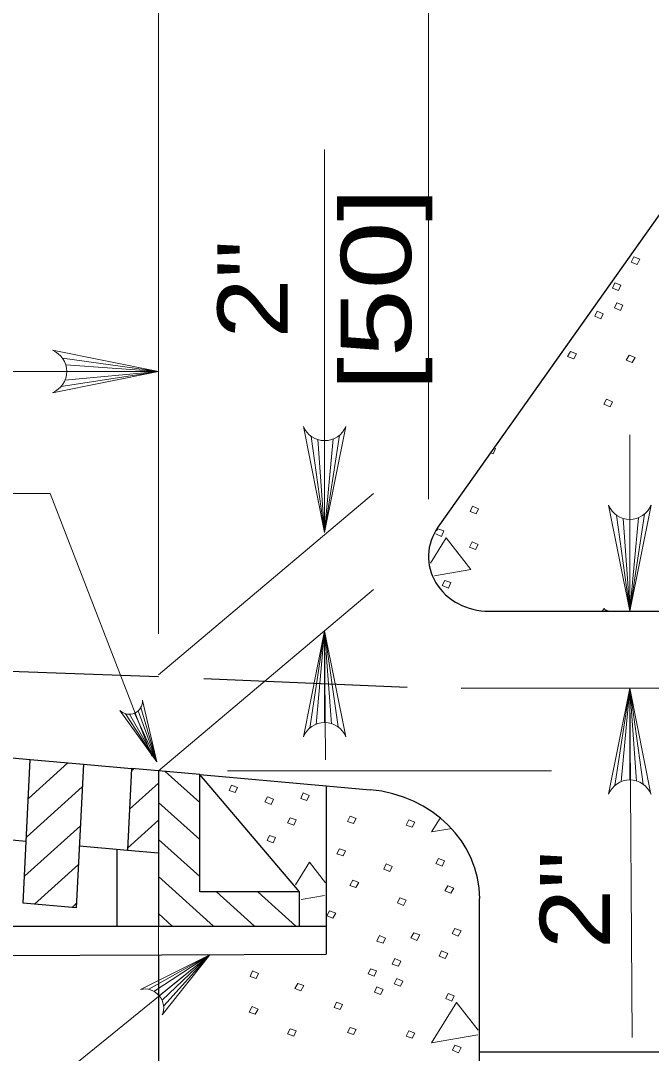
# Model space of a CAD drawing. Extents: x 1083.1 to 1123, y 697.4 to 741.4.
# Drawn here: x 1091.119 to 1092.52, y 703.761 to 706.055 of the extents above; entities that cross this region are included whole.
import ezdxf
from ezdxf.enums import TextEntityAlignment as Align

# ---------------------------------------------------------------- set-up
doc = ezdxf.new("R2010")
doc.units = 0
doc.header["$LTSCALE"] = 0.062
doc.layers.add('1', color=7, linetype='Continuous', lineweight=13)

msp = doc.modelspace()

# ---------------------------------------------------------------- linework, layer by layer
at = {"layer": '1'}
for p, q in [((1091.42492, 704.693), (1091.42492, 706.78342)), ((1092.02483, 704.99242), (1092.02483, 706.78958)), ((1091.79425, 705.769), (1091.79425, 704.91825)), ((1091.21167, 705.3055), (1091.42492, 705.27567)), ((1091.21892, 705.29067), (1091.42492, 705.27567)), ((1091.42492, 705.27567), (1088.74, 705.27567)), ((1091.20917, 705.24267), (1091.42492, 705.27567)), ((1091.21733, 705.2565), (1091.42492, 705.27567)), ((1091.22108, 705.27567), (1091.42492, 705.27567)), ((1091.76442, 705.1315), (1091.79425, 704.91825)), ((1091.77917, 705.12433), (1091.79425, 704.91825)), ((1091.82725, 705.13408), (1091.79425, 704.91825)), ((1091.81342, 705.12592), (1091.79425, 704.91825)), ((1091.79425, 705.12208), (1091.79425, 704.91825)), ((1092.47208, 705.13492), (1092.47208, 704.74317)), ((1091.053, 705.00442), (1091.18417, 705.00442)), ((1091.41017, 704.4215), (1091.18417, 705.00442)), ((1091.42492, 704.60175), (1091.90275, 705.005)), ((1092.44225, 704.95642), (1092.47208, 704.74317)), ((1092.457, 704.94925), (1092.47208, 704.74317)), ((1092.50508, 704.959), (1092.47208, 704.74317)), ((1092.49125, 704.95083), (1092.47208, 704.74317)), ((1092.47208, 704.947), (1092.47208, 704.74317)), ((1092.04342, 704.92175), (1092.04567, 704.92642)), ((1092.0645, 704.90625), (1092.02967, 704.85008)), ((1091.42492, 704.3885), (1091.90275, 704.79175)), ((1092.41492, 704.7495), (1092.41092, 704.74317)), ((1092.41983, 704.74317), (1092.41492, 704.7495)), ((1092.419, 704.74317), (1092.42008, 704.74542)), ((1092.42008, 704.74542), (1092.4255, 704.74317)), ((1091.76125, 704.48367), (1091.79425, 704.6995)), ((1091.77508, 704.49183), (1091.79425, 704.6995)), ((1091.79425, 704.6995), (1091.79617, 704.41275)), ((1091.79425, 704.49567), (1091.79425, 704.6995)), ((1091.80933, 704.49342), (1091.79425, 704.6995)), ((1091.82408, 704.48625), (1091.79425, 704.6995)), ((1092.43908, 704.35633), (1092.47208, 704.57217)), ((1092.45292, 704.3645), (1092.47208, 704.57217)), ((1092.47208, 704.57217), (1092.47733, 703.79633)), ((1092.47208, 704.36833), (1092.47208, 704.57217)), ((1092.48717, 704.36608), (1092.47208, 704.57217)), ((1092.50192, 704.35892), (1092.47208, 704.57217)), ((1091.38575, 704.52933), (1091.42117, 704.40875)), ((1091.35175, 704.5155), (1091.42117, 704.40875)), ((1091.36108, 704.51458), (1091.42117, 704.40875)), ((1091.37217, 704.51708), (1091.42117, 704.40875)), ((1091.37967, 704.52192), (1091.42117, 704.40875)), ((1091.136, 704.32733), (1091.22392, 704.40642)), ((1091.42492, 704.38842), (1091.42492, 704.3885)), ((1091.57858, 704.3885), (1092.29825, 704.3885)), ((1091.51675, 704.31825), (1091.44025, 704.38708)), ((1091.51675, 704.38025), (1091.51675, 704.38033)), ((1091.13167, 704.24117), (1091.25583, 704.35292)), ((1091.36075, 704.30333), (1091.42492, 704.36108)), ((1091.51675, 704.236), (1091.42492, 704.31858)), ((1091.35642, 704.21717), (1091.42492, 704.27883)), ((1091.12733, 704.155), (1091.25158, 704.26667)), ((1091.51675, 704.15375), (1091.42492, 704.23633)), ((1091.76042, 704.18583), (1091.72917, 704.13542)), ((1091.796, 704.14025), (1091.76042, 704.18583)), ((1091.14975, 704.09283), (1091.24725, 704.18058)), ((1091.54733, 704.04392), (1091.42492, 704.15408)), ((1091.63875, 704.04392), (1091.55425, 704.11992)), ((1091.73017, 704.04392), (1091.64567, 704.11992)), ((1091.7385, 704.11867), (1091.73708, 704.11992)), ((1091.233, 704.08542), (1091.24292, 704.09442)), ((1091.74192, 704.10267), (1091.79417, 704.11175)), ((1091.45583, 704.04392), (1091.42492, 704.07167)), ((1091.42492, 704.04392), (1091.42492, 703.97992)), ((1091.40333, 703.90342), (1091.53892, 703.97992)), ((1091.41483, 703.89875), (1091.53892, 703.97992)), ((1091.42667, 703.88892), (1091.53892, 703.97992)), ((1091.43317, 703.879), (1091.53892, 703.97992)), ((1091.43667, 703.86692), (1091.53892, 703.97992)), ((1092.13525, 703.81233), (1092.08733, 703.87383))]:
    msp.add_line(p, q, dxfattribs=at)
at = {"layer": '1', "lineweight": 25}
for p, q in [((1092.1595, 704.74317), (1094.45958, 704.74317)), ((1091.42542, 704.5975), (1091.0745, 704.61033)), ((1091.97725, 704.57375), (1091.52617, 704.59333)), ((1092.55433, 704.57217), (1092.09758, 704.57167)), ((1091.02217, 704.42433), (1091.14025, 704.41383)), ((1091.14025, 704.41342), (1091.14075, 704.41383)), ((1091.25833, 704.40333), (1091.36525, 704.39383)), ((1091.36508, 704.38942), (1091.36942, 704.39342)), ((1091.51675, 704.38033), (1091.42492, 704.3885)), ((1091.51675, 704.38033), (1091.79742, 704.35525)), ((1091.7385, 704.11992), (1091.51675, 704.38025)), ((1091.79742, 704.35525), (1091.89567, 704.3465)), ((1091.01317, 704.24308), (1091.13125, 704.23258)), ((1091.24933, 704.222), (1091.35617, 704.21258)), ((1091.33267, 704.21467), (1091.33267, 704.04392)), ((1091.35617, 704.21258), (1091.42492, 704.20642)), ((1092.13858, 702.97792), (1092.13858, 704.10533)), ((1088.74, 704.04392), (1091.42492, 704.04392)), ((1091.7385, 704.04392), (1091.79742, 704.04392)), ((1088.03742, 703.9655), (1091.79742, 703.9815)), ((1091.42492, 703.97992), (1091.42492, 702.97792)), ((1092.13858, 703.76442), (1093.4365, 703.76442))]:
    msp.add_line(p, q, dxfattribs=at)
for points in [[(1092.759, 707.22517), (1092.58783, 705.69442), (1092.046, 704.92958)], [(1091.42492, 704.3885), (1091.36525, 704.39383), (1091.35625, 704.2135)], [(1091.42492, 704.38842), (1091.42492, 704.20642), (1091.42492, 704.04392), (1091.7385, 704.04392), (1091.7385, 704.11992), (1091.51675, 704.11992), (1091.51675, 704.38025)], [(1091.79742, 704.35525), (1091.79742, 704.04392), (1091.79742, 703.9815)]]:
    msp.add_lwpolyline(points, dxfattribs=at)
at = {"layer": '1'}
for points in [[(1092.48117, 705.53008), (1092.49467, 705.52525), (1092.48833, 705.51317), (1092.47492, 705.51883)], [(1092.439, 705.47275), (1092.45242, 705.46708), (1092.44708, 705.45575), (1092.43358, 705.46058)], [(1092.4435, 705.42833), (1092.45692, 705.42267), (1092.45158, 705.41133), (1092.43808, 705.417)], [(1092.3995, 705.40967), (1092.41292, 705.404), (1092.40758, 705.39275), (1092.39408, 705.39842)], [(1092.34017, 705.32), (1092.35367, 705.31517), (1092.34742, 705.30383), (1092.33392, 705.30867)], [(1092.47042, 705.31192), (1092.48383, 705.30708), (1092.47758, 705.29575), (1092.46408, 705.30058)], [(1092.42008, 705.21417), (1092.43358, 705.2085), (1092.42817, 705.19717), (1092.41475, 705.20283)], [(1092.12283, 704.97658), (1092.13633, 704.97092), (1092.131, 704.95958), (1092.1175, 704.96442)], [(1092.122, 704.89733), (1092.13542, 704.89167), (1092.12917, 704.88042), (1092.11567, 704.88525)], [(1092.06092, 704.81167), (1092.07442, 704.80683), (1092.069, 704.79475), (1092.0555, 704.80042)], [(1091.58742, 704.35717), (1091.60083, 704.3515), (1091.5955, 704.34017), (1091.582, 704.345)], [(1091.66708, 704.33092), (1091.6805, 704.32608), (1091.67517, 704.314), (1091.66167, 704.31967)], [(1091.74658, 704.33967), (1091.76008, 704.334), (1091.75467, 704.32267), (1091.74125, 704.32758)], [(1091.71733, 704.28442), (1091.73083, 704.27958), (1091.72542, 704.26825), (1091.712, 704.27308)], [(1091.85117, 704.28767), (1091.86458, 704.28275), (1091.85833, 704.2715), (1091.84483, 704.27633)], [(1091.98133, 704.27958), (1091.99483, 704.27467), (1091.9885, 704.26342), (1091.97508, 704.26825)], [(1091.6715, 704.24533), (1091.685, 704.2405), (1091.67967, 704.22842), (1091.66617, 704.23408)], [(1091.82692, 704.21575), (1091.84033, 704.21083), (1091.835, 704.19958), (1091.8215, 704.20442)], [(1091.93108, 704.18175), (1091.9445, 704.17608), (1091.93917, 704.16483), (1091.92567, 704.1705)], [(1092.04692, 704.19392), (1092.06042, 704.189), (1092.055, 704.17692), (1092.0415, 704.18258)], [(1091.8565, 704.14617), (1091.87, 704.14058), (1091.86375, 704.12925), (1091.85025, 704.13408)], [(1092.06758, 704.13325), (1092.081, 704.12842), (1092.07475, 704.11708), (1092.06125, 704.122)], [(1091.96158, 704.10658), (1091.97508, 704.10175), (1091.96967, 704.08967), (1091.95625, 704.09533)], [(1091.80533, 704.0775), (1091.81883, 704.07267), (1091.8125, 704.06133), (1091.79908, 704.06625)], [(1091.91583, 704.02258), (1091.92925, 704.01692), (1091.92392, 704.00558), (1091.91042, 704.01042)], [(1091.99217, 704.029), (1092.00558, 704.02417), (1091.99933, 704.01208), (1091.98583, 704.01775)], [(1092.08375, 704.03875), (1092.09717, 704.03308), (1092.09092, 704.02175), (1092.07742, 704.02742)], [(1092.05408, 703.98858), (1092.06758, 703.983), (1092.06217, 703.97167), (1092.04867, 703.97733)], [(1091.94992, 703.97167), (1091.96342, 703.966), (1091.958, 703.95467), (1091.9445, 703.9595)], [(1091.63383, 703.94417), (1091.64733, 703.9385), (1091.64192, 703.92725), (1091.62842, 703.93208)], [(1091.89608, 703.949), (1091.9095, 703.94417), (1091.90408, 703.93283), (1091.89067, 703.93775)], [(1091.73442, 703.91667), (1091.74783, 703.91183), (1091.74158, 703.89975), (1091.72808, 703.90542)], [(1091.91042, 703.90858), (1091.92392, 703.903), (1091.9185, 703.89167), (1091.905, 703.89733)], [(1091.95442, 703.92725), (1091.96792, 703.92158), (1091.9625, 703.91025), (1091.949, 703.91592)], [(1092.06842, 703.89408), (1092.08192, 703.88925), (1092.07658, 703.87708), (1092.06308, 703.88275)], [(1091.63292, 703.865), (1091.64642, 703.85933), (1091.64008, 703.848), (1091.62667, 703.85283)], [(1091.82058, 703.87467), (1091.83408, 703.86983), (1091.82867, 703.8585), (1091.81525, 703.86333)], [(1091.71733, 703.81567), (1091.73083, 703.81083), (1091.72542, 703.7995), (1091.712, 703.80442)], [(1091.85117, 703.81892), (1091.86458, 703.81408), (1091.85833, 703.80275), (1091.84483, 703.80758)], [(1091.98133, 703.81083), (1091.99483, 703.806), (1091.9885, 703.79467), (1091.97508, 703.7995)], [(1092.08375, 703.77933), (1092.09717, 703.7745), (1092.09183, 703.76233), (1092.07833, 703.768)]]:
    msp.add_lwpolyline(points, close=True, dxfattribs=at)
for points in [[(1091.18933, 705.2285), (1091.42492, 705.27567), (1091.18933, 705.32275)], [(1091.84142, 705.15383), (1091.79425, 704.91825), (1091.74717, 705.15383)], [(1092.17075, 705.10558), (1092.17408, 705.10425), (1092.16867, 705.09292), (1092.16308, 705.09492)], [(1092.51925, 704.97875), (1092.47208, 704.74317), (1092.425, 704.97875)], [(1092.04567, 704.92642), (1092.05917, 704.92158), (1092.05375, 704.9095), (1092.04108, 704.91483)], [(1092.03808, 704.82175), (1092.11925, 704.83592), (1092.0645, 704.90625)], [(1091.74708, 704.46392), (1091.79425, 704.6995), (1091.84133, 704.46392)], [(1092.42492, 704.33658), (1092.47208, 704.57217), (1092.51917, 704.33658)], [(1091.33958, 704.52267), (1091.42117, 704.40875), (1091.38967, 704.54525)], [(1092.05083, 704.28375), (1092.03167, 704.25292), (1092.07667, 704.26083)], [(1091.53892, 703.97992), (1090.60408, 703.22075), (1090.33183, 703.22075)], [(1091.38525, 703.903), (1091.53892, 703.97992), (1091.43317, 703.84658)], [(1092.08733, 703.87383), (1092.03167, 703.78417), (1092.13467, 703.80225)]]:
    msp.add_lwpolyline(points, dxfattribs=at)
at = {"layer": '1', "lineweight": 25}
msp.add_lwpolyline([(1091.12442, 704.09508), (1091.14025, 704.41383), (1091.25833, 704.40333), (1091.2425, 704.08458)], close=True, dxfattribs=at)
at = {"layer": '1'}
for centre, start, end in [((1091.17035, 705.27568), 292.08605, 67.91218), ((1091.79422, 705.17286), 202.08782, 337.91395), ((1092.47205, 704.99777), 202.08782, 337.91395), ((1091.79428, 704.44489), 22.08782, 157.91395), ((1092.47211, 704.31756), 22.08782, 157.91395)]:
    msp.add_arc(centre, 0.05085, start, end, dxfattribs=at)
at = {"layer": '1', "lineweight": 25}
for centre, major_axis, start_param, end_param in [((1092.15953, 704.86438), (-0.1347, 0), 5.7150373, 7.8539816), ((1091.86919, 704.10529), (0.2694, 0), 6.2831853, 7.7553847)]:
    msp.add_ellipse(centre, major_axis=major_axis, ratio=0.899905, start_param=start_param, end_param=end_param, dxfattribs=at)
at = {"layer": '1'}
for centre, major_axis, ratio, start_param, end_param in [((1091.35999, 704.54413), (0.02844, -0.00844), 0.999895, 4.2402426, 6.6108557), ((1091.39869, 703.86627), (0.0288, -0.02772), 0.899905, 0.2742024, 2.6448156)]:
    msp.add_ellipse(centre, major_axis=major_axis, ratio=ratio, start_param=start_param, end_param=end_param, dxfattribs=at)

# ---------------------------------------------------------------- texts
for s, width, p in [('[50]', 1.3, (1091.98617, 705.45821)), ('2"', 1.15, (1091.71217, 705.45821)), ('2"', 1.15, (1092.42825, 704.10204))]:
    msp.add_text(s, height=0.156, rotation=90, dxfattribs=dict(at, width=width)).set_placement(p, align=Align.CENTER)

doc.saveas('drawing.dxf')
